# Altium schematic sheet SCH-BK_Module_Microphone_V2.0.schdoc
size 267 x 168 mm
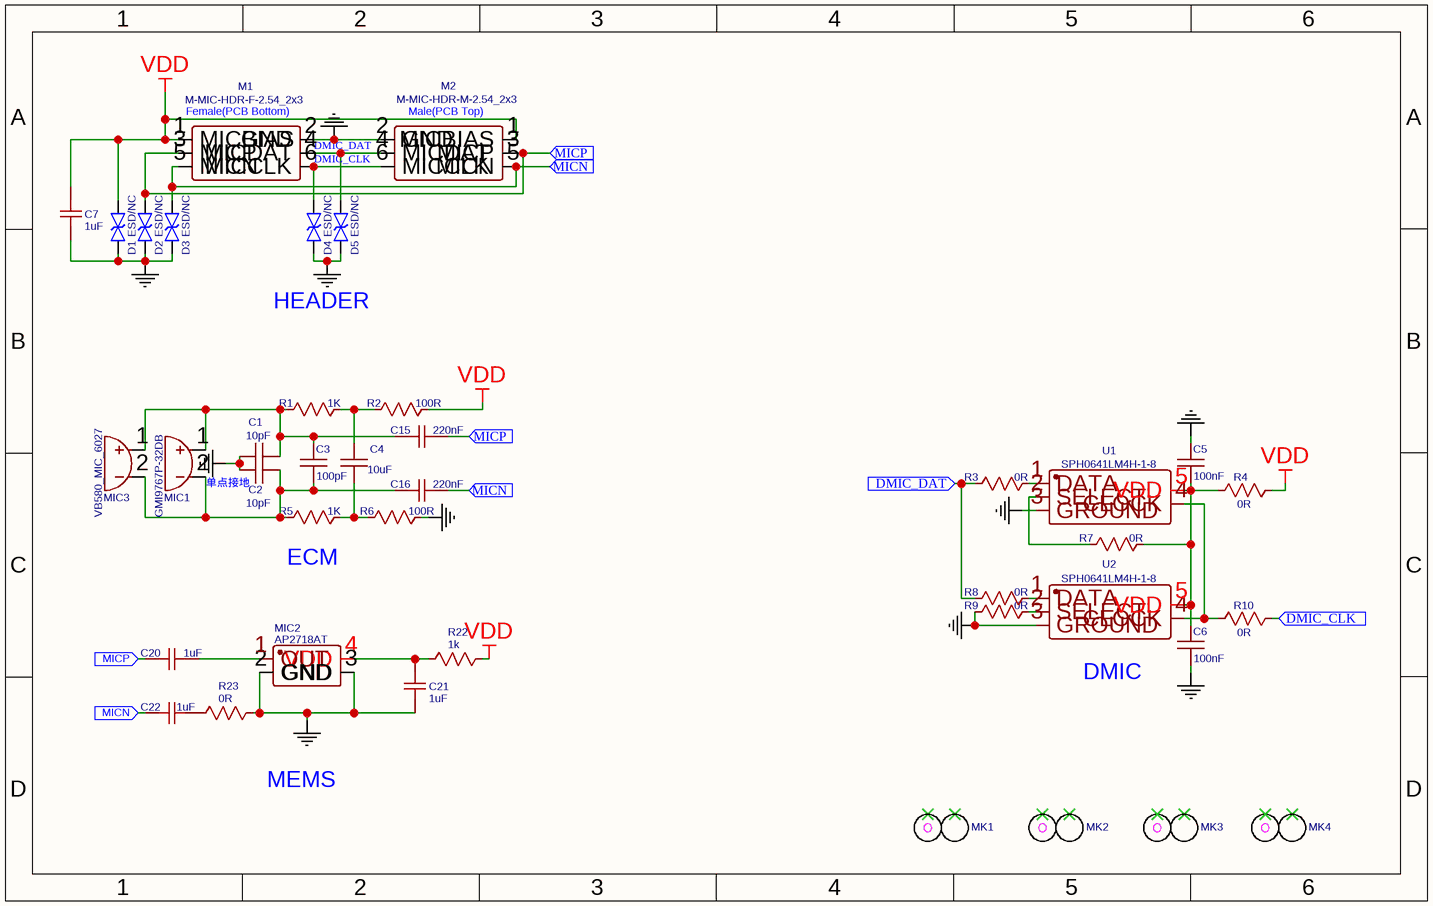
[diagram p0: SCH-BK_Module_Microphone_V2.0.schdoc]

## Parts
C1  10pF  [C0402]
C2  10pF  [C0402]
C3  100pF  [C0402]
C4  10uF  [C0603]
C5  100nF  [C0402]
C6  100nF  [C0402]
C7  1uF  [C0402]
C15  220nF  [C0402]
C16  220nF  [C0402]
C20  1uF  [C0402]
C21  1uF  [C0402]
C22  1uF  [C0402]
D1  ESD/NC  [ESD0402]
D2  ESD/NC  [ESD0402]
D3  ESD/NC  [ESD0402]
D4  ESD/NC  [ESD0402]
D5  ESD/NC  [ESD0402]
M1  M-MIC-HDR-F-2.54_2x3  [M-MIC-HDR-F-2.54_2X3]
M2  M-MIC-HDR-M-2.54_2x3  [M-MIC-HDR-M-2.54_2X3]
MIC1  GMI9767P-32DB  [MIC-TH_BD9.7-P2.54-D0.8-L-FD]
MIC2  AP2718AT  [MSM42A2718H9R]
MIC3  VB580_MIC_6027  [MIC-TH_BD6.0-P1.90-D0.4-L]
MK1  MARK  [MARK]  (value not drawn)
MK2  MARK  [MARK]  (value not drawn)
MK3  MARK  [MARK]  (value not drawn)
MK4  MARK  [MARK]  (value not drawn)
R1  1K  [R0402]
R2  100R  [R0402]
R3  0R  [R0402]
R4  0R  [R0402]
R5  1K  [R0402]
R6  100R  [R0402]
R7  0R  [R0402]
R8  0R  [R0402]
R9  0R  [R0402]
R10  0R  [R0402]
R22  1k  [R0402]
R23  0R  [R0402]
U1  SPH0641LM4H-1-8  [MIC-SPH0641LM4H-1]
U2  SPH0641LM4H-1-8  [MIC-SPH0641LM4H-1]

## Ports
DMIC_CLK (in), DMIC_DAT (in), MICN (in), MICP (in)

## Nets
GGND: C1.1 C2.1 C5.1 C6.2 C7.2 C21.2 D1.2 D2.2 D3.2 D4.2 D5.2 M1.2(GND) M2.2(GND) MIC2.2(GND) MIC2.3(GND) R6.2 R9.1 R23.2 U1.3(GROUND) U2.3(GROUND)
VDD: C7.1 D1.1 M1.1(MICBIAS) M2.1(MICBIAS) R2.2 R4.2 R22.2
DMIC_CLK: R10.2 ; port DMIC_CLK
DMIC_CLK: D4.1 M1.6(MICCLK) M2.6(MICCLK)  [a separate net that carries the same name]
DMIC_DAT: R3.1 R8.1 ; port DMIC_DAT
DMIC_DAT: D5.1 M1.4(MICDAT) M2.4(MICDAT)  [a separate net that carries the same name]
MICN: C16.2 C22.1 D3.1 M1.5(MICN) M2.5(MICN) ; port MICN
MICP: C15.2 C20.1 D2.1 M1.3(MICP) M2.3(MICP) ; port MICP
NetC1_2: C1.2 C3.1 C15.1 MIC1.1 MIC3.1 R1.1
NetC2_2: C2.2 C3.2 C16.1 MIC1.2 MIC3.2 R5.1
NetC4_1: C4.1 R1.2 R2.1
NetC4_2: C4.2 R5.2 R6.1
NetC5_2: C5.2 C6.1 R4.1 R7.2 U1.5(VDD) U2.5(VDD)
NetC20_2: C20.2 MIC2.1(OUT)
NetC21_1: C21.1 MIC2.4(VDD) R22.1
NetC22_2: C22.2 R23.1
NetR3_2: R3.2 U1.1(DATA)
NetR7_1: R7.1 U1.2(SELECT)
NetR8_2: R8.2 U2.1(DATA)
NetR9_2: R9.2 U2.2(SELECT)
NetR10_1: R10.1 U1.4(CLOCK) U2.4(CLOCK)

Not connected (* = marked no-connect by the designer): MK1 1* 2*; MK2 1* 2*; MK3 1* 2*; MK4 1* 2*

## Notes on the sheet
- (near M1) Female(PCB Bottom)
- (near M2) Male(PCB Top)
- HEADER
- (near MIC1) 单点接地
- (near R5) ECM
- (near U2) DMIC
- MEMS

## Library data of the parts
C1 C2 = 10pF: Manufacturer: AVX; Manufacturer Part Number: 0805ZC105KAT2A; APN: C071-0
C3 = 100pF: Manufacturer: AVX; Manufacturer Part Number: 0805ZC105KAT2A; APN: C071-0
C4 = 10uF: Manufacturer: AVX; Manufacturer Part Number: 0805ZC105KAT2A; APN: C071-0
C5 C6 = 100nF: Manufacturer: AVX; Manufacturer Part Number: 0805ZC105KAT2A; APN: C071-0
C7 C20-C22 = 1uF: nameAlias: Value(F); Contributor: LCEDA_Lib
C15 C16 = 220nF: nameAlias: Value(F); Contributor: LCEDA_Lib
D1-D5 = ESD/NC: Contributor: D-MAN
M1 = M-MIC-HDR-F-2.54_2x3: Contributor: qunshan.xu
M2 = M-MIC-HDR-M-2.54_2x3: Contributor: qunshan.xu
MIC1 = GMI9767P-32DB: Manufacturer: INGHAi(赢海); Contributor: LCSC
MIC2 = AP2718AT: Manufacturer: ALLPOWER; Contributor: shuguang.zhang
MIC3 = VB580_MIC_6027: Manufacturer: 华镇; Manufacturer Part: 0010M-VB580-MIC627; Contributor: LCSC
MK1-MK4 = MARK: Contributor: qunshan.xu
R1 R5 = 1K: nameAlias: Value(Ω); Contributor: LCEDA_Lib
R2 R6 = 100R: nameAlias: Value(Ω); Contributor: LCEDA_Lib
R3 R4 R7-R10 R23 = 0R: nameAlias: Value(Ω); Contributor: LCEDA_Lib
R22 = 1k: nameAlias: Value(Ω); Contributor: LCEDA_Lib
U1 U2 = SPH0641LM4H-1-8: Manufacturer: Knowles(楼氏); Contributor: LCSC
